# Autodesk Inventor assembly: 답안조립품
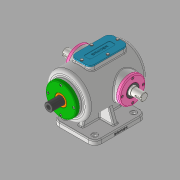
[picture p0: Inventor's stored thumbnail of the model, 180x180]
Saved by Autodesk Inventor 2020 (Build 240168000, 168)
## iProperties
Created: 2021-11
Part Number: 답안조립품
Document SubType Name: Assembly
Designer: Administrator
Author: Administrator
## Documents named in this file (15)
- C:\Users\Administrator\Desktop\711106V1026\답안조립품.iam
- C:\Users\Administrator\Desktop\711106V1026\본체.ipt
- C:\Users\Administrator\Desktop\711106V1026\베어링 6205.ipt
- 베어링 6205.ipt
- C:\Users\Administrator\Desktop\711106V1026\볼트 M4x0.7.ipt
- C:\Users\Administrator\Desktop\711106V1026\부시.ipt
- C:\Users\Administrator\Desktop\711106V1026\상부커버.ipt
- C:\Users\Administrator\Desktop\711106V1026\슬라이드 커버.ipt
- C:\Users\Administrator\Desktop\711106V1026\슬라이드.ipt
- C:\Users\Administrator\Desktop\711106V1026\오일실.ipt
- 오일실.ipt
- C:\Users\Administrator\Desktop\711106V1026\육각머리볼트 M4.ipt
- C:\Users\Administrator\Desktop\711106V1026\축 커버.ipt
- C:\Users\Administrator\Desktop\711106V1026\편심축.ipt
- C:\Users\Administrator\Desktop\711106V1026\축 커버_MIR.ipt
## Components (12 placed, 1 different names)
1. M4x0.7:1 — 각도:1
2. M4x0.7:3
3. M4x0.7:4
4. M4x0.7:5
5. M4x0.7:6
6. M4x0.7:7
7. M4x0.7:8
8. M4x0.7:9
9. M4x0.7:2 — 각도:5
10. M4x0.7:10
11. M4x0.7:11
12. M4x0.7:12
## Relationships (2: Angle 2)
- 각도:1 [Angle]: M4x0.7:1
- 각도:5 [Angle]: M4x0.7:2
